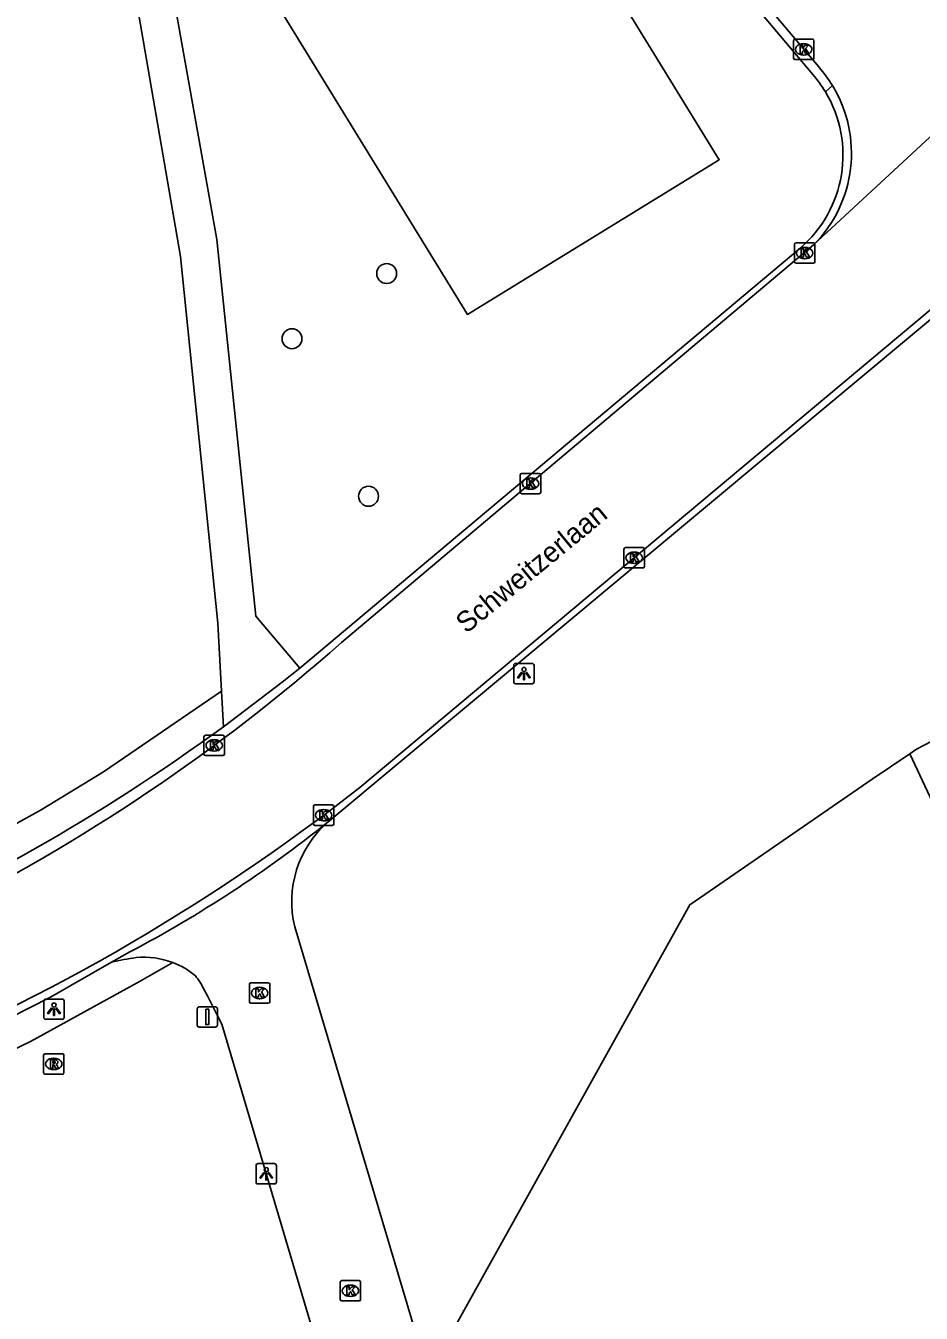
# Model space of a CAD drawing. Extents: x 162157 to 163165, y 378998 to 380775.
# Drawn here: x 162640.4 to 162684.3, y 380157.8 to 380221 of the extents above; entities that cross this region are included whole.
import ezdxf

# ---------------------------------------------------------------- set-up
doc = ezdxf.new("R2010")
doc.units = 0
for name, color, linetype in [('IMGEO_Boom', 7, 'Continuous'), ('IMGEO_Grasland_overig', 7, 'Continuous'), ('IMGEO_Groenvoorziening', 7, 'Continuous'), ('IMGEO_Kolk', 7, 'Continuous'), ('IMGEO_Lichtpunt', 7, 'Continuous'), ('IMGEO_Naaldbos', 7, 'Continuous'), ('IMGEO_Openbare_ruimte_label', 7, 'Continuous'), ('IMGEO_Rijbaan_lokaal_gesloten', 7, 'Continuous'), ('IMGEO_Rijbaan_lokaal_open', 7, 'Continuous'), ('IMGEO_Rioolput', 7, 'Continuous'), ('IMGEO_Verkeersbordpaal', 7, 'Continuous'), ('IMGEO_Voetpad_halfverhard', 7, 'Continuous')]:
    doc.layers.add(name, color=color, linetype=linetype)

msp = doc.modelspace()

# ---------------------------------------------------------------- linework, layer by layer
at = {"layer": 'IMGEO_Boom'}
for centre in [(162658.074, 380208.812), (162653.427, 380205.612), (162657.183, 380197.88)]:
    msp.add_circle(centre, 0.489, dxfattribs=at)
at = {"layer": 'IMGEO_Grasland_overig'}
msp.add_lwpolyline([(162683.75, 380185.241), (162691.517, 380168.667), (162698.902, 380163.627)], dxfattribs=at)
at = {"layer": 'IMGEO_Groenvoorziening'}
msp.add_lwpolyline([(162658.591, 380240.123), (162674.394, 380214.393), (162662.039, 380206.804), (162646.235, 380232.534), (162658.591, 380240.123)], dxfattribs=at)
at = {"layer": 'IMGEO_Kolk'}
for p, q in [((162678.037, 380219.388), (162678.037, 380220.24)), ((162678.112, 380220.314), (162678.964, 380220.314)), ((162679.038, 380220.24), (162679.038, 380219.388)), ((162678.525, 380220.094), (162678.55, 380220.094)), ((162678.964, 380219.314), (162678.112, 380219.314)), ((162678.548, 380219.534), (162678.523, 380219.534)), ((162678.084, 380209.391), (162678.084, 380210.243)), ((162678.159, 380210.317), (162679.011, 380210.317)), ((162678.572, 380210.097), (162678.597, 380210.097)), ((162679.085, 380210.243), (162679.085, 380209.391)), ((162678.595, 380209.537), (162678.57, 380209.537)), ((162679.011, 380209.317), (162678.159, 380209.317)), ((162664.63, 380198.077), (162664.63, 380198.929)), ((162664.705, 380199.003), (162665.557, 380199.003)), ((162665.118, 380198.783), (162665.143, 380198.783)), ((162665.631, 380198.929), (162665.631, 380198.077)), ((162665.141, 380198.223), (162665.116, 380198.223)), ((162665.557, 380198.003), (162664.705, 380198.003)), ((162669.716, 380194.432), (162669.716, 380195.284)), ((162669.791, 380195.358), (162670.643, 380195.358)), ((162670.204, 380195.138), (162670.229, 380195.138)), ((162670.717, 380195.284), (162670.717, 380194.432)), ((162670.643, 380194.358), (162669.791, 380194.358)), ((162670.227, 380194.578), (162670.202, 380194.578)), ((162649.109, 380185.222), (162649.109, 380186.074)), ((162649.184, 380186.148), (162650.036, 380186.148)), ((162650.11, 380186.074), (162650.11, 380185.222)), ((162649.597, 380185.928), (162649.622, 380185.928)), ((162650.036, 380185.148), (162649.184, 380185.148)), ((162649.62, 380185.368), (162649.595, 380185.368)), ((162654.48, 380181.799), (162654.48, 380182.651)), ((162654.555, 380182.725), (162655.407, 380182.725)), ((162654.968, 380182.505), (162654.993, 380182.505)), ((162655.481, 380182.651), (162655.481, 380181.799)), ((162655.407, 380181.725), (162654.555, 380181.725)), ((162654.991, 380181.945), (162654.966, 380181.945)), ((162651.338, 380173.071), (162651.338, 380173.923)), ((162651.413, 380173.997), (162652.265, 380173.997)), ((162651.826, 380173.777), (162651.851, 380173.777)), ((162652.339, 380173.923), (162652.339, 380173.071)), ((162652.265, 380172.997), (162651.413, 380172.997)), ((162651.849, 380173.217), (162651.824, 380173.217)), ((162655.795, 380158.455), (162655.795, 380159.307)), ((162655.87, 380159.381), (162656.722, 380159.381)), ((162656.283, 380159.161), (162656.308, 380159.161)), ((162656.796, 380159.307), (162656.796, 380158.455)), ((162656.722, 380158.381), (162655.87, 380158.381)), ((162656.306, 380158.601), (162656.281, 380158.601))]:
    msp.add_line(p, q, dxfattribs=at)
for points in [[(162678.037, 380219.388), (162678.037, 380220.24)], [(162678.112, 380220.314), (162678.964, 380220.314)], [(162679.038, 380220.24), (162679.038, 380219.388)], [(162678.358, 380220.014), (162678.481, 380220.014), (162678.481, 380219.863), (162678.611, 380220.014), (162678.775, 380220.014), (162678.629, 380219.863), (162678.782, 380219.614), (162678.63, 380219.614), (162678.545, 380219.778), (162678.481, 380219.711), (162678.481, 380219.614), (162678.358, 380219.614), (162678.358, 380220.014)], [(162678.964, 380219.314), (162678.112, 380219.314)], [(162678.084, 380209.391), (162678.084, 380210.243)], [(162678.159, 380210.317), (162679.011, 380210.317)], [(162679.085, 380210.243), (162679.085, 380209.391)], [(162678.405, 380210.017), (162678.528, 380210.017), (162678.528, 380209.866), (162678.658, 380210.017), (162678.822, 380210.017), (162678.676, 380209.866), (162678.829, 380209.617), (162678.677, 380209.617), (162678.592, 380209.781), (162678.528, 380209.714), (162678.528, 380209.617), (162678.405, 380209.617), (162678.405, 380210.017)], [(162679.011, 380209.317), (162678.159, 380209.317)], [(162664.63, 380198.077), (162664.63, 380198.929)], [(162664.705, 380199.003), (162665.557, 380199.003)], [(162665.631, 380198.929), (162665.631, 380198.077)], [(162664.951, 380198.703), (162665.074, 380198.703), (162665.074, 380198.552), (162665.204, 380198.703), (162665.368, 380198.703), (162665.222, 380198.552), (162665.375, 380198.303), (162665.223, 380198.303), (162665.138, 380198.467), (162665.074, 380198.4), (162665.074, 380198.303), (162664.951, 380198.303), (162664.951, 380198.703)], [(162665.557, 380198.003), (162664.705, 380198.003)], [(162669.716, 380194.432), (162669.716, 380195.284)], [(162669.791, 380195.358), (162670.643, 380195.358)], [(162670.037, 380195.058), (162670.16, 380195.058), (162670.16, 380194.907), (162670.29, 380195.058), (162670.454, 380195.058), (162670.308, 380194.907), (162670.461, 380194.658), (162670.309, 380194.658), (162670.224, 380194.822), (162670.16, 380194.755), (162670.16, 380194.658), (162670.037, 380194.658), (162670.037, 380195.058)], [(162670.717, 380195.284), (162670.717, 380194.432)], [(162670.643, 380194.358), (162669.791, 380194.358)], [(162649.109, 380185.222), (162649.109, 380186.074)], [(162649.184, 380186.148), (162650.036, 380186.148)], [(162650.11, 380186.074), (162650.11, 380185.222)], [(162649.43, 380185.848), (162649.553, 380185.848), (162649.553, 380185.697), (162649.683, 380185.848), (162649.847, 380185.848), (162649.701, 380185.697), (162649.854, 380185.448), (162649.702, 380185.448), (162649.617, 380185.612), (162649.553, 380185.545), (162649.553, 380185.448), (162649.43, 380185.448), (162649.43, 380185.848)], [(162650.036, 380185.148), (162649.184, 380185.148)], [(162654.48, 380181.799), (162654.48, 380182.651)], [(162654.555, 380182.725), (162655.407, 380182.725)], [(162654.801, 380182.425), (162654.924, 380182.425), (162654.924, 380182.274), (162655.054, 380182.425), (162655.218, 380182.425), (162655.072, 380182.274), (162655.225, 380182.025), (162655.073, 380182.025), (162654.988, 380182.189), (162654.924, 380182.122), (162654.924, 380182.025), (162654.801, 380182.025), (162654.801, 380182.425)], [(162655.481, 380182.651), (162655.481, 380181.799)], [(162655.407, 380181.725), (162654.555, 380181.725)], [(162651.338, 380173.071), (162651.338, 380173.923)], [(162651.413, 380173.997), (162652.265, 380173.997)], [(162651.659, 380173.697), (162651.782, 380173.697), (162651.782, 380173.546), (162651.912, 380173.697), (162652.076, 380173.697), (162651.93, 380173.546), (162652.083, 380173.297), (162651.931, 380173.297), (162651.846, 380173.461), (162651.782, 380173.394), (162651.782, 380173.297), (162651.659, 380173.297), (162651.659, 380173.697)], [(162652.339, 380173.923), (162652.339, 380173.071)], [(162652.265, 380172.997), (162651.413, 380172.997)], [(162655.795, 380158.455), (162655.795, 380159.307)], [(162655.87, 380159.381), (162656.722, 380159.381)], [(162656.116, 380159.081), (162656.239, 380159.081), (162656.239, 380158.93), (162656.369, 380159.081), (162656.533, 380159.081), (162656.387, 380158.93), (162656.54, 380158.681), (162656.388, 380158.681), (162656.303, 380158.845), (162656.239, 380158.778), (162656.239, 380158.681), (162656.116, 380158.681), (162656.116, 380159.081)], [(162656.796, 380159.307), (162656.796, 380158.455)], [(162656.722, 380158.381), (162655.87, 380158.381)]]:
    msp.add_lwpolyline(points, dxfattribs=at)
for centre, start, end in [((162678.114, 380220.238), 91.55205, 178.44795), ((162678.114, 380220.238), 91.55205, 178.44795), ((162678.962, 380220.238), 1.55205, 88.44795), ((162678.962, 380220.238), 1.55205, 88.44795), ((162678.114, 380219.39), 181.55205, 268.44795), ((162678.114, 380219.39), 181.55205, 268.44795), ((162678.962, 380219.39), 271.55205, 358.44795), ((162678.962, 380219.39), 271.55205, 358.44795), ((162678.161, 380210.241), 91.55205, 178.44795), ((162678.161, 380210.241), 91.55205, 178.44795), ((162679.009, 380210.241), 1.55205, 88.44795), ((162679.009, 380210.241), 1.55205, 88.44795), ((162678.161, 380209.393), 181.55205, 268.44795), ((162678.161, 380209.393), 181.55205, 268.44795), ((162679.009, 380209.393), 271.55205, 358.44795), ((162679.009, 380209.393), 271.55205, 358.44795), ((162664.707, 380198.927), 91.55205, 178.44795), ((162664.707, 380198.927), 91.55205, 178.44795), ((162665.555, 380198.927), 1.55205, 88.44795), ((162665.555, 380198.927), 1.55205, 88.44795), ((162664.707, 380198.079), 181.55205, 268.44795), ((162664.707, 380198.079), 181.55205, 268.44795), ((162665.555, 380198.079), 271.55205, 358.44795), ((162665.555, 380198.079), 271.55205, 358.44795), ((162669.793, 380195.282), 91.55205, 178.44795), ((162669.793, 380195.282), 91.55205, 178.44795), ((162670.641, 380195.282), 1.55205, 88.44795), ((162670.641, 380195.282), 1.55205, 88.44795), ((162669.793, 380194.434), 181.55205, 268.44795), ((162669.793, 380194.434), 181.55205, 268.44795), ((162670.641, 380194.434), 271.55205, 358.44795), ((162670.641, 380194.434), 271.55205, 358.44795), ((162649.186, 380186.072), 91.55205, 178.44795), ((162649.186, 380186.072), 91.55205, 178.44795), ((162650.034, 380186.072), 1.55205, 88.44795), ((162650.034, 380186.072), 1.55205, 88.44795), ((162649.186, 380185.224), 181.55205, 268.44795), ((162649.186, 380185.224), 181.55205, 268.44795), ((162650.034, 380185.224), 271.55205, 358.44795), ((162650.034, 380185.224), 271.55205, 358.44795), ((162654.557, 380182.649), 91.55205, 178.44795), ((162654.557, 380182.649), 91.55205, 178.44795), ((162655.405, 380182.649), 1.55205, 88.44795), ((162655.405, 380182.649), 1.55205, 88.44795), ((162654.557, 380181.801), 181.55205, 268.44795), ((162654.557, 380181.801), 181.55205, 268.44795), ((162655.405, 380181.801), 271.55205, 358.44795), ((162655.405, 380181.801), 271.55205, 358.44795), ((162651.415, 380173.921), 91.55205, 178.44795), ((162651.415, 380173.921), 91.55205, 178.44795), ((162652.263, 380173.921), 1.55205, 88.44795), ((162652.263, 380173.921), 1.55205, 88.44795), ((162651.415, 380173.073), 181.55205, 268.44795), ((162651.415, 380173.073), 181.55205, 268.44795), ((162652.263, 380173.073), 271.55205, 358.44795), ((162652.263, 380173.073), 271.55205, 358.44795), ((162655.872, 380159.305), 91.55205, 178.44795), ((162655.872, 380159.305), 91.55205, 178.44795), ((162656.72, 380159.305), 1.55205, 88.44795), ((162656.72, 380159.305), 1.55205, 88.44795), ((162655.872, 380158.457), 181.55205, 268.44795), ((162655.872, 380158.457), 181.55205, 268.44795), ((162656.72, 380158.457), 271.55205, 358.44795), ((162656.72, 380158.457), 271.55205, 358.44795)]:
    msp.add_arc(centre, 0.0765, start, end, dxfattribs=at)
for centre, major_axis, ratio, start_param, end_param in [((162678.524, 380219.814), (-0.387, 0.002), 0.722429, 4.712389, 7.853982), ((162678.549, 380219.814), (-0.39, 0.002), 0.717154, 1.570796, 4.712389), ((162678.571, 380209.817), (-0.387, 0.002), 0.722429, 4.712389, 7.853982), ((162678.596, 380209.817), (-0.39, 0.002), 0.717154, 1.570796, 4.712389), ((162665.117, 380198.503), (-0.387, 0.002), 0.722429, 4.712389, 7.853982), ((162665.142, 380198.503), (-0.39, 0.002), 0.717154, 1.570796, 4.712389), ((162670.203, 380194.858), (-0.387, 0.002), 0.722429, 4.712389, 7.853982), ((162670.228, 380194.858), (-0.39, 0.002), 0.717154, 1.570796, 4.712389), ((162649.596, 380185.648), (-0.387, 0.002), 0.722429, 4.712389, 7.853982), ((162649.621, 380185.648), (-0.39, 0.002), 0.717154, 1.570796, 4.712389), ((162654.967, 380182.225), (-0.387, 0.002), 0.722429, 4.712389, 7.853982), ((162654.992, 380182.225), (-0.39, 0.002), 0.717154, 1.570796, 4.712389), ((162651.825, 380173.497), (-0.387, 0.002), 0.722429, 4.712389, 7.853982), ((162651.85, 380173.497), (-0.39, 0.002), 0.717154, 1.570796, 4.712389), ((162656.282, 380158.881), (-0.387, 0.002), 0.722429, 4.712389, 7.853982), ((162656.307, 380158.881), (-0.39, 0.002), 0.717154, 1.570796, 4.712389)]:
    msp.add_ellipse(centre, major_axis=major_axis, ratio=ratio, start_param=start_param, end_param=end_param, dxfattribs=at)
at = {"layer": 'IMGEO_Lichtpunt'}
for p, q in [((162664.31, 380189.578), (162664.31, 380188.771)), ((162664.31, 380189.578), (162664.31, 380188.771)), ((162665.212, 380189.673), (162664.404, 380189.673)), ((162665.212, 380189.673), (162664.404, 380189.673)), ((162665.306, 380188.771), (162665.306, 380189.578)), ((162665.306, 380188.771), (162665.306, 380189.578)), ((162664.404, 380188.677), (162665.212, 380188.677)), ((162664.404, 380188.677), (162665.212, 380188.677)), ((162641.252, 380173.105), (162641.252, 380172.298)), ((162641.252, 380173.105), (162641.252, 380172.298)), ((162642.154, 380173.2), (162641.346, 380173.2)), ((162642.154, 380173.2), (162641.346, 380173.2)), ((162642.248, 380172.298), (162642.248, 380173.105)), ((162642.248, 380172.298), (162642.248, 380173.105)), ((162641.346, 380172.204), (162642.154, 380172.204)), ((162641.346, 380172.204), (162642.154, 380172.204)), ((162651.667, 380165.027), (162651.667, 380164.22)), ((162651.667, 380165.027), (162651.667, 380164.22)), ((162652.569, 380165.122), (162651.761, 380165.122)), ((162652.569, 380165.122), (162651.761, 380165.122)), ((162652.663, 380164.22), (162652.663, 380165.027)), ((162652.663, 380164.22), (162652.663, 380165.027)), ((162651.761, 380164.126), (162652.569, 380164.126)), ((162651.761, 380164.126), (162652.569, 380164.126))]:
    msp.add_line(p, q, dxfattribs=at)
for points in [[(162664.684, 380189.242), (162664.723, 380189.214), (162664.535, 380188.952), (162664.497, 380188.979), (162664.684, 380189.242)], [(162664.896, 380189.214), (162664.934, 380189.241), (162665.121, 380188.979), (162665.082, 380188.951), (162664.896, 380189.214)], [(162664.786, 380189.194), (162664.833, 380189.194), (162664.833, 380188.872), (162664.786, 380188.872), (162664.786, 380189.194)], [(162641.626, 380172.769), (162641.665, 380172.741), (162641.477, 380172.479), (162641.439, 380172.506), (162641.626, 380172.769)], [(162641.728, 380172.721), (162641.775, 380172.721), (162641.775, 380172.399), (162641.728, 380172.399), (162641.728, 380172.721)], [(162641.838, 380172.741), (162641.876, 380172.768), (162642.063, 380172.506), (162642.024, 380172.478), (162641.838, 380172.741)], [(162652.041, 380164.691), (162652.08, 380164.663), (162651.892, 380164.401), (162651.854, 380164.428), (162652.041, 380164.691)], [(162652.143, 380164.643), (162652.19, 380164.643), (162652.19, 380164.321), (162652.143, 380164.321), (162652.143, 380164.643)], [(162652.253, 380164.663), (162652.291, 380164.69), (162652.478, 380164.428), (162652.439, 380164.4), (162652.253, 380164.663)]]:
    msp.add_lwpolyline(points, dxfattribs=at)
for centre in [(162664.809, 380189.376), (162641.751, 380172.903), (162652.166, 380164.825)]:
    msp.add_circle(centre, 0.0994, dxfattribs=at)
for centre, start, end in [((162664.404, 380189.578), 90, 180), ((162664.404, 380189.578), 90, 180), ((162665.212, 380189.578), 0, 90), ((162665.212, 380189.578), 0, 90), ((162664.404, 380188.771), 180, 270), ((162664.404, 380188.771), 180, 270), ((162665.212, 380188.771), 270, 0), ((162665.212, 380188.771), 270, 360), ((162641.346, 380173.105), 90, 180), ((162641.346, 380173.105), 90, 180), ((162642.154, 380173.105), 0, 90), ((162642.154, 380173.105), 0, 90), ((162641.346, 380172.298), 180, 270), ((162641.346, 380172.298), 180, 270), ((162642.154, 380172.298), 270, 0), ((162642.154, 380172.298), 270, 360), ((162651.761, 380165.027), 90, 180), ((162651.761, 380165.027), 90, 180), ((162652.569, 380165.027), 0, 90), ((162652.569, 380165.027), 0, 90), ((162651.761, 380164.22), 180, 270), ((162651.761, 380164.22), 180, 270), ((162652.569, 380164.22), 270, 0), ((162652.569, 380164.22), 270, 360)]:
    msp.add_arc(centre, 0.0946, start, end, dxfattribs=at)
at = {"layer": 'IMGEO_Naaldbos'}
for points in [[(162683.75, 380185.241), (162684.072, 380185.457), (162686.321, 380186.65), (162691.653, 380188.938)], [(162558.368, 380174.087), (162583.616, 380170.389), (162588.773, 380169.872), (162593.099, 380169.694), (162600.363, 380169.808), (162606.842, 380170.376), (162609.282, 380170.72), (162616.087, 380172.172), (162619.638, 380173.162), (162622.542, 380174.087), (162626.235, 380175.389), (162630.152, 380176.949), (162633.119, 380178.279), (162636.443, 380179.901), (162641.115, 380182.49), (162644.172, 380184.351), (162649.967, 380188.317)], [(162660.112, 380154.748), (162672.953, 380177.826), (162681.901, 380184), (162683.75, 380185.241)], [(162647.581, 380174.986), (162645.981, 380174.076), (162640.599, 380171.121), (162636.367, 380169.074), (162632.926, 380167.558), (162626.656, 380165.185), (162621.454, 380163.733), (162614.788, 380162.187), (162609.105, 380161.182), (162598.999, 380160.213), (162591.971, 380160.192), (162585.021, 380160.577), (162577.372, 380161.631), (162570.251, 380162.647)]]:
    msp.add_lwpolyline(points, dxfattribs=at)
at = {"layer": 'IMGEO_Rijbaan_lokaal_gesloten'}
for points in [[(162679.271, 380218.95), (162653.003, 380250), (162650.632, 380252.803), (162650.282, 380253.2), (162645.496, 380258.949)], [(162649.683, 380253.342), (162652.499, 380250), (162678.976, 380218.586)], [(162693.063, 380223.251), (162679.022, 380210.216)], [(162699.326, 380219.441), (162688.108, 380209.839), (162656.75, 380183.582)], [(162679.599, 380217.731), (162679.942, 380218.043)], [(162679.022, 380210.216), (162655.849, 380190.696)], [(162678.341, 380210.04), (162653.805, 380189.445)], [(162653.805, 380189.445), (162652.951, 380188.748), (162650.061, 380186.558)]]:
    msp.add_lwpolyline(points, dxfattribs=at)
for centre, radius, start, end in [((162674.521, 380214.734), 6.351, 31.39791, 41.59028), ((162674.36, 380214.568), 6.12, 31.12077, 41.03751), ((162674.442, 380214.626), 6.019, 310.36977, 31.05126), ((162674.494, 380214.716), 6.384, 315.18056, 31.41166), ((162595.208, 380259.25), 91.526, 281.47051, 311.49531), ((162592.179, 380265.933), 98.238, 280.17472, 306.10024), ((162595.293, 380261.894), 99.547, 291.47114, 308.12363)]:
    msp.add_arc(centre, radius, start, end, dxfattribs=at)
at = {"layer": 'IMGEO_Rijbaan_lokaal_open'}
for points in [[(162655.18, 380181.877), (162688.009, 380209.266)], [(162660.112, 380154.748), (162653.567, 380176.746)], [(162644.576, 380175.002), (162645.479, 380175.516)], [(162637.579, 380171.262), (162641.578, 380173.298), (162644.576, 380175.002)], [(162656.386, 380150.406), (162649.981, 380171.964), (162649.708, 380172.51), (162649.431, 380173.056), (162649.291, 380173.329), (162649.086, 380173.72)]]:
    msp.add_lwpolyline(points, dxfattribs=at)
for centre, radius, start, end in [((162616.796, 380229.838), 61.43, 297.83509, 308.67107), ((162658.587, 380177.987), 5.171, 131.21248, 193.88502), ((162647.946, 380160.961), 14.44, 98.61168, 103.49695), ((162646.154, 380171.34), 3.915, 68.61862, 95.41589), ((162646.455, 380171.804), 3.375, 48.6302, 70.51579), ((162646.413, 380172.425), 2.97, 25.84471, 40.06583)]:
    msp.add_arc(centre, radius, start, end, dxfattribs=at)
at = {"layer": 'IMGEO_Rioolput'}
for p, q in [((162641.24, 380169.588), (162641.24, 380170.44)), ((162641.315, 380170.514), (162642.167, 380170.514)), ((162641.728, 380170.294), (162641.753, 380170.294)), ((162642.241, 380170.44), (162642.241, 380169.588)), ((162641.751, 380169.734), (162641.726, 380169.734)), ((162642.167, 380169.514), (162641.315, 380169.514))]:
    msp.add_line(p, q, dxfattribs=at)
for points in [[(162641.24, 380169.588), (162641.24, 380170.44)], [(162641.315, 380170.514), (162642.167, 380170.514)], [(162642.241, 380170.44), (162642.241, 380169.588)], [(162641.829, 380170.212), (162641.577, 380170.214), (162641.577, 380169.814)], [(162641.577, 380169.814), (162641.701, 380169.814), (162641.701, 380169.976), (162641.712, 380169.976)], [(162641.755, 380170.133), (162641.701, 380170.133), (162641.701, 380170.052)], [(162641.701, 380170.052), (162641.753, 380170.052)], [(162641.759, 380169.947), (162641.83, 380169.814), (162641.97, 380169.814), (162641.905, 380169.94)], [(162642.167, 380169.514), (162641.315, 380169.514)]]:
    msp.add_lwpolyline(points, dxfattribs=at)
for centre, radius, start, end in [((162641.317, 380170.438), 0.0765, 91.55205, 178.44795), ((162641.317, 380170.438), 0.0765, 91.55205, 178.44795), ((162642.165, 380170.438), 0.0765, 1.55205, 88.44795), ((162642.165, 380170.438), 0.0765, 1.55205, 88.44795), ((162641.711, 380169.923), 0.0533, 26.02933, 88.69889), ((162641.737, 380170.241), 0.19, 274.7715, 282.96867), ((162641.761, 380170.037), 0.0964, 77.00612, 93.18647), ((162641.775, 380170.094), 0.0378, 276.66336, 79.67722), ((162641.828, 380170.102), 0.109, 350.36119, 89.41601), ((162641.826, 380170.102), 0.112, 277.58423, 350.98172), ((162641.81, 380169.887), 0.108, 29.51342, 73.79051), ((162641.317, 380169.59), 0.0765, 181.55205, 268.44795), ((162641.317, 380169.59), 0.0765, 181.55205, 268.44795), ((162642.165, 380169.59), 0.0765, 271.55205, 358.44795), ((162642.165, 380169.59), 0.0765, 271.55205, 358.44795)]:
    msp.add_arc(centre, radius, start, end, dxfattribs=at)
for centre, major_axis, ratio, start_param, end_param in [((162641.727, 380170.014), (-0.387, 0.002), 0.722429, 4.712389, 7.853982), ((162641.752, 380170.014), (-0.39, 0.002), 0.717154, 1.570796, 4.712389)]:
    msp.add_ellipse(centre, major_axis=major_axis, ratio=ratio, start_param=start_param, end_param=end_param, dxfattribs=at)
at = {"layer": 'IMGEO_Verkeersbordpaal'}
for p, q in [((162648.876, 380172.82), (162649.666, 380172.82)), ((162649.666, 380172.82), (162648.876, 380172.82)), ((162648.776, 380171.92), (162648.776, 380172.72)), ((162648.776, 380172.72), (162648.776, 380171.92)), ((162649.766, 380172.72), (162649.766, 380171.92)), ((162649.766, 380171.92), (162649.766, 380172.72)), ((162649.666, 380171.82), (162648.876, 380171.82)), ((162648.876, 380171.82), (162649.666, 380171.82))]:
    msp.add_line(p, q, dxfattribs=at)
msp.add_lwpolyline([(162649.196, 380172.695), (162649.346, 380172.695), (162649.346, 380171.945), (162649.196, 380171.945), (162649.196, 380172.695)], dxfattribs=at)
for centre, start, end in [((162648.876, 380172.72), 90, 180), ((162648.876, 380172.72), 90, 180), ((162649.666, 380172.72), 0, 90), ((162649.666, 380172.72), 360, 90), ((162648.876, 380171.92), 180, 270), ((162648.876, 380171.92), 180, 270), ((162649.666, 380171.92), 270, 0), ((162649.666, 380171.92), 270, 0)]:
    msp.add_arc(centre, 0.1, start, end, dxfattribs=at)
at = {"layer": 'IMGEO_Voetpad_halfverhard'}
for points in [[(162623.843, 380294.36), (162627.777, 380287.672), (162630.973, 380280.301), (162634.541, 380268.954), (162639.9, 380250), (162644.236, 380231.272), (162647.96, 380209.653), (162649.788, 380191.643), (162649.967, 380188.317)], [(162641.035, 380252.871), (162641.836, 380250), (162645.963, 380231.675), (162649.738, 380210.474), (162651.648, 380191.988), (162653.805, 380189.445)], [(162649.967, 380188.317), (162650.061, 380186.558)]]:
    msp.add_lwpolyline(points, dxfattribs=at)

# ---------------------------------------------------------------- texts
at = {"layer": 'IMGEO_Openbare_ruimte_label'}
msp.add_text('Schweitzerlaan', height=1, rotation=39.43862, dxfattribs=at).set_placement((162661.983, 380191.106))

doc.saveas('drawing.dxf')
